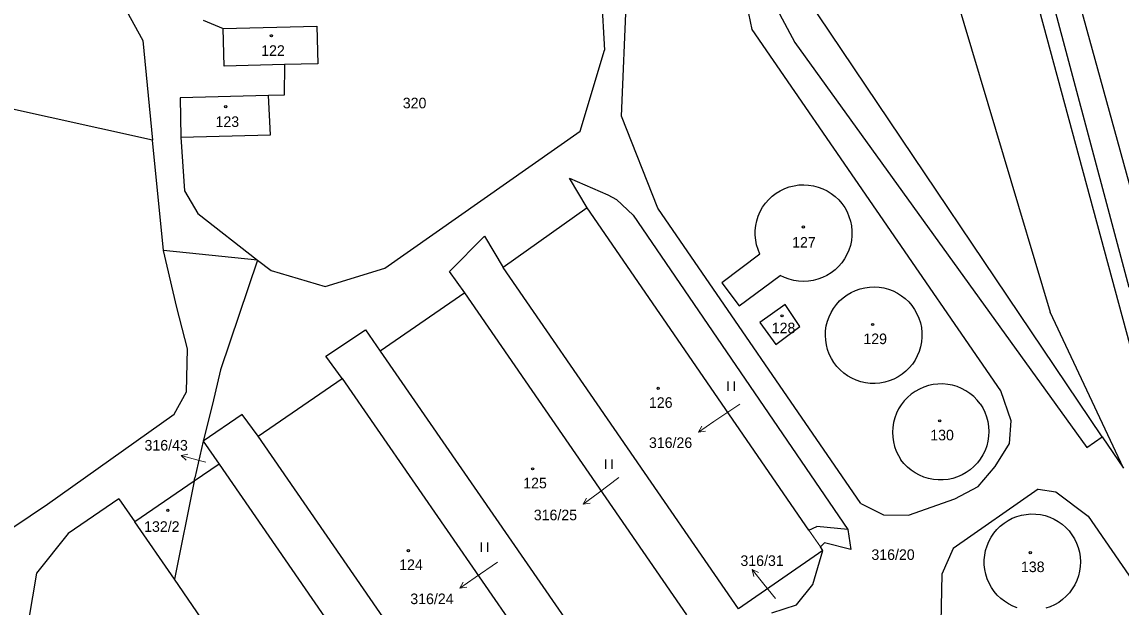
# Model space of a CAD drawing. Extents: x -765428 to -762163, y -1107632 to -1104975.
# Drawn here: x -763826.2 to -763649.6, y -1106955.1 to -1106861.1 of the extents above; entities that cross this region are included whole.
import ezdxf
from ezdxf.enums import TextEntityAlignment as Align

# ---------------------------------------------------------------- set-up
doc = ezdxf.new("R2010")
doc.units = 0
doc.header["$LTSCALE"] = 0.68
for name, color, linetype, lineweight in [('1', 7, 'Continuous', 25), ('3', 7, 'Continuous', 25), ('4', 7, 'Continuous', 13), ('5', 7, 'Continuous', 25), ('7', 7, 'Continuous', 13)]:
    doc.layers.add(name, color=color, linetype=linetype, lineweight=lineweight)
doc.layers.add('2', color=7, linetype='Continuous')

msp = doc.modelspace()

# ---------------------------------------------------------------- linework, layer by layer
at = {"layer": '1'}
for p, q in [((-763729.84, -1106876.2), (-763724.72, -1106752.96)), ((-763674.43, -1106815.86), (-763648.22, -1106912.79)), ((-763671.61, -1106816.67), (-763648.34, -1106903.67)), ((-763685.8, -1106824.68), (-763661.01, -1106907.69)), ((-763658.9, -1106848.62), (-763644.06, -1106902.56)), ((-763733.28, -1106852.94), (-763732.61, -1106865.62)), ((-763652.64, -1106927.72), (-763703.4, -1106852.31)), ((-763810.93, -1106856.45), (-763806.76, -1106864.07)), ((-763708.89, -1106862.32), (-763709.99, -1106856.84)), ((-763705.7, -1106857.45), (-763702.02, -1106864.4)), ((-763797.08, -1106860.79), (-763793.86, -1106862.12)), ((-763793.86, -1106862.12), (-763778.83, -1106861.76)), ((-763793.68, -1106868.18), (-763793.86, -1106862.12)), ((-763778.83, -1106861.76), (-763778.65, -1106867.81)), ((-763668.92, -1106920.34), (-763708.89, -1106862.32)), ((-763806.76, -1106864.07), (-763805.23, -1106880.1)), ((-763736.52, -1106878.66), (-763732.61, -1106865.62)), ((-763702.02, -1106864.4), (-763655.1, -1106929.44)), ((-763784.03, -1106867.94), (-763793.68, -1106868.18)), ((-763784.03, -1106867.94), (-763784.07, -1106872.85)), ((-763778.65, -1106867.81), (-763784.03, -1106867.94)), ((-763805.23, -1106880.1), (-763850.56, -1106870)), ((-763784.07, -1106872.85), (-763786.56, -1106872.91)), ((-763786.56, -1106872.91), (-763800.79, -1106873.27)), ((-763800.79, -1106873.27), (-763800.66, -1106879.61)), ((-763786.26, -1106879.25), (-763786.56, -1106872.91)), ((-763724.04, -1106891), (-763729.84, -1106876.2)), ((-763800.66, -1106879.61), (-763786.26, -1106879.25)), ((-763800.66, -1106879.61), (-763800.09, -1106888.21)), ((-763767.86, -1106900.62), (-763736.52, -1106878.66)), ((-763803.44, -1106897.82), (-763805.23, -1106880.1)), ((-763738.22, -1106886.17), (-763732.08, -1106888.88)), ((-763735.38, -1106890.95), (-763738.22, -1106886.17)), ((-763800.09, -1106888.21), (-763797.94, -1106891.84)), ((-763732.08, -1106888.88), (-763730.66, -1106889.62)), ((-763730.66, -1106889.62), (-763728, -1106892.15)), ((-763797.94, -1106891.84), (-763788.32, -1106899.34)), ((-763735.38, -1106890.95), (-763748.9, -1106900.52)), ((-763699.75, -1106942.73), (-763735.38, -1106890.95)), ((-763728, -1106892.15), (-763693.51, -1106942.61)), ((-763691.41, -1106938.45), (-763724.04, -1106891)), ((-763757.48, -1106901.19), (-763751.89, -1106895.5)), ((-763751.89, -1106895.5), (-763748.9, -1106900.52)), ((-763801.32, -1106906.94), (-763803.44, -1106897.82)), ((-763788.32, -1106899.34), (-763803.44, -1106897.82)), ((-763788.32, -1106899.34), (-763794.28, -1106917)), ((-763788.32, -1106899.34), (-763786.17, -1106901.01)), ((-763707.61, -1106898.39), (-763713.73, -1106902.99)), ((-763786.17, -1106901.01), (-763777.49, -1106903.61)), ((-763777.49, -1106903.61), (-763767.86, -1106900.62)), ((-763711.05, -1106955.37), (-763748.9, -1106900.52)), ((-763755.04, -1106904.61), (-763757.48, -1106901.19)), ((-763710.95, -1106906.71), (-763704.38, -1106901.81)), ((-763755.04, -1106904.61), (-763768.62, -1106914)), ((-763719.34, -1106956.36), (-763755.04, -1106904.61)), ((-763713.73, -1106902.99), (-763710.95, -1106906.71)), ((-763799.59, -1106913.59), (-763801.32, -1106906.94)), ((-763649.23, -1106932.76), (-763661.01, -1106907.69)), ((-763707.64, -1106909.36), (-763705.08, -1106912.93)), ((-763777.39, -1106914.8), (-763771.01, -1106910.53)), ((-763771.01, -1106910.53), (-763768.62, -1106914)), ((-763705.08, -1106912.93), (-763701.2, -1106910.04)), ((-763799.77, -1106920.51), (-763799.59, -1106913.59)), ((-763774.76, -1106918.36), (-763777.39, -1106914.8)), ((-763768.62, -1106914), (-763730.65, -1106968.92)), ((-763794.28, -1106917), (-763795.57, -1106922.48)), ((-763788.24, -1106927.65), (-763774.76, -1106918.36)), ((-763774.76, -1106918.36), (-763738.81, -1106970.36)), ((-763801.72, -1106924.09), (-763799.77, -1106920.51)), ((-763667.27, -1106925.18), (-763668.92, -1106920.34)), ((-763795.57, -1106922.48), (-763797.06, -1106928.41)), ((-763822.07, -1106938.55), (-763801.72, -1106924.09)), ((-763790.83, -1106924.13), (-763797.06, -1106928.41)), ((-763788.24, -1106927.65), (-763790.83, -1106924.13)), ((-763667.5, -1106928.81), (-763667.27, -1106925.18)), ((-763797.06, -1106928.41), (-763798.41, -1106934.35)), ((-763797.06, -1106928.41), (-763794.52, -1106932.12)), ((-763750.25, -1106982.66), (-763788.24, -1106927.65)), ((-763669.8, -1106932.49), (-763667.5, -1106928.81)), ((-763655.1, -1106929.44), (-763652.64, -1106927.72)), ((-763652.64, -1106927.72), (-763649.23, -1106932.76)), ((-763794.52, -1106932.12), (-763798.51, -1106934.86)), ((-763794.52, -1106932.12), (-763758.29, -1106984.57)), ((-763672.58, -1106935.74), (-763669.8, -1106932.49)), ((-763798.51, -1106934.86), (-763798.41, -1106934.35)), ((-763798.51, -1106934.86), (-763808.06, -1106941.41)), ((-763662.89, -1106936.13), (-763676.56, -1106945.69)), ((-763676.32, -1106937.69), (-763672.58, -1106935.74)), ((-763662.89, -1106936.13), (-763660.09, -1106936.58)), ((-763810.62, -1106937.71), (-763818.75, -1106943.29)), ((-763810.62, -1106937.71), (-763808.06, -1106941.41)), ((-763683.77, -1106940.31), (-763676.32, -1106937.69)), ((-763660.09, -1106936.58), (-763654.9, -1106940.48)), ((-763827.64, -1106942.32), (-763822.07, -1106938.55)), ((-763691.41, -1106938.45), (-763687.78, -1106940.28)), ((-763687.78, -1106940.28), (-763683.77, -1106940.31)), ((-763654.9, -1106940.48), (-763622.05, -1106988.12)), ((-763818.75, -1106943.29), (-763823.87, -1106949.65)), ((-763699.75, -1106942.73), (-763698.45, -1106942.12)), ((-763693.51, -1106942.61), (-763698.45, -1106942.12)), ((-763693.51, -1106942.61), (-763693.04, -1106945.86)), ((-763697.9, -1106945.43), (-763697.22, -1106944.76)), ((-763693.04, -1106945.86), (-763697.22, -1106944.76)), ((-763697.52, -1106945.98), (-763711.05, -1106955.37)), ((-763699.14, -1106951.48), (-763697.52, -1106945.98)), ((-763697.52, -1106945.98), (-763697.9, -1106945.43)), ((-763676.56, -1106945.69), (-763678.37, -1106949.8)), ((-763823.87, -1106949.65), (-763825.16, -1106957.25)), ((-763678.37, -1106949.8), (-763678.57, -1106957.56)), ((-763770.1, -1106996.39), (-763801.7, -1106950.62)), ((-763701.74, -1106954.74), (-763699.14, -1106951.48)), ((-763705.7, -1106956.04), (-763701.74, -1106954.74))]:
    msp.add_line(p, q, dxfattribs=at)
for points in [[(-763707.61, -1106898.39), (-763707.915, -1106897.665), (-763708.146, -1106896.914), (-763708.299, -1106896.143), (-763708.374, -1106895.36), (-763708.369, -1106894.574), (-763708.284, -1106893.792), (-763708.122, -1106893.023), (-763707.882, -1106892.275), (-763707.568, -1106891.554), (-763707.183, -1106890.869), (-763706.73, -1106890.226), (-763706.215, -1106889.632), (-763705.642, -1106889.093), (-763705.018, -1106888.615), (-763704.349, -1106888.203), (-763703.641, -1106887.86), (-763702.903, -1106887.59), (-763702.141, -1106887.397), (-763701.363, -1106887.281), (-763700.578, -1106887.245), (-763699.793, -1106887.288), (-763699.016, -1106887.41), (-763698.256, -1106887.61), (-763697.52, -1106887.886), (-763696.815, -1106888.235), (-763696.15, -1106888.653), (-763695.53, -1106889.136), (-763694.962, -1106889.68), (-763694.451, -1106890.278), (-763694.004, -1106890.924), (-763693.625, -1106891.613), (-763693.317, -1106892.336), (-763693.083, -1106893.087), (-763692.927, -1106893.857), (-763692.849, -1106894.64), (-763692.851, -1106895.426), (-763692.932, -1106896.208), (-763693.092, -1106896.977), (-763693.329, -1106897.727), (-763693.64, -1106898.449), (-763694.023, -1106899.136), (-763694.473, -1106899.78), (-763694.986, -1106900.376), (-763695.557, -1106900.917), (-763696.179, -1106901.398), (-763696.846, -1106901.813), (-763697.553, -1106902.158), (-763698.29, -1106902.431), (-763699.051, -1106902.627), (-763699.828, -1106902.746), (-763700.614, -1106902.785), (-763701.399, -1106902.745), (-763702.176, -1106902.626), (-763702.937, -1106902.429), (-763703.674, -1106902.156), (-763704.38, -1106901.81)], [(-763695.74, -1106915.8), (-763696.143, -1106915.145), (-763696.479, -1106914.453), (-763696.745, -1106913.731), (-763696.939, -1106912.986), (-763697.057, -1106912.226), (-763697.1, -1106911.458), (-763697.066, -1106910.689), (-763696.957, -1106909.928), (-763696.773, -1106909.181), (-763696.515, -1106908.456), (-763696.187, -1106907.76), (-763695.792, -1106907.1), (-763695.333, -1106906.482), (-763694.816, -1106905.913), (-763694.245, -1106905.398), (-763693.625, -1106904.942), (-763692.963, -1106904.549), (-763692.266, -1106904.224), (-763691.54, -1106903.97)], [(-763691.54, -1106903.97), (-763690.787, -1106903.788), (-763690.019, -1106903.682), (-763689.244, -1106903.654), (-763688.471, -1106903.702), (-763687.706, -1106903.828), (-763686.958, -1106904.029), (-763686.233, -1106904.304), (-763685.54, -1106904.65), (-763684.884, -1106905.064), (-763684.273, -1106905.54), (-763683.713, -1106906.076), (-763683.209, -1106906.664), (-763682.766, -1106907.3), (-763682.389, -1106907.977), (-763682.081, -1106908.688), (-763681.845, -1106909.427), (-763681.685, -1106910.185), (-763681.601, -1106910.955), (-763681.594, -1106911.73), (-763681.665, -1106912.502), (-763681.812, -1106913.263), (-763682.035, -1106914.005), (-763682.33, -1106914.722), (-763682.696, -1106915.405), (-763683.127, -1106916.049), (-763683.621, -1106916.646), (-763684.172, -1106917.191), (-763684.775, -1106917.678), (-763685.423, -1106918.103), (-763686.111, -1106918.461), (-763686.83, -1106918.748), (-763687.575, -1106918.962), (-763688.338, -1106919.101), (-763689.11, -1106919.163), (-763689.885, -1106919.148), (-763690.654, -1106919.056), (-763691.411, -1106918.887), (-763692.146, -1106918.643), (-763692.854, -1106918.328), (-763693.527, -1106917.943), (-763694.158, -1106917.493), (-763694.741, -1106916.982), (-763695.27, -1106916.416), (-763695.74, -1106915.8)], [(-763701.2, -1106910.04), (-763703.55, -1106906.5), (-763707.64, -1106909.36)], [(-763672.23, -1106922.43), (-763672.722, -1106921.824), (-763673.272, -1106921.27), (-763673.875, -1106920.774), (-763674.524, -1106920.341), (-763675.214, -1106919.975), (-763675.936, -1106919.68), (-763676.685, -1106919.458), (-763677.452, -1106919.313), (-763678.23, -1106919.244), (-763679.01, -1106919.254), (-763679.786, -1106919.343), (-763680.549, -1106919.508), (-763681.291, -1106919.748), (-763682.006, -1106920.062), (-763682.686, -1106920.446), (-763683.324, -1106920.896), (-763683.914, -1106921.407), (-763684.45, -1106921.975), (-763684.926, -1106922.593), (-763685.338, -1106923.256), (-763685.682, -1106923.957), (-763685.953, -1106924.689), (-763686.151, -1106925.444), (-763686.271, -1106926.215), (-763686.314, -1106926.995), (-763686.279, -1106927.775), (-763686.166, -1106928.547), (-763685.977, -1106929.304), (-763685.712, -1106930.039), (-763685.375, -1106930.743), (-763684.97, -1106931.41)], [(-763672.23, -1106922.43), (-763671.814, -1106923.097), (-763671.467, -1106923.803), (-763671.193, -1106924.541), (-763670.995, -1106925.302), (-763670.875, -1106926.079), (-763670.834, -1106926.864), (-763670.871, -1106927.65), (-763670.988, -1106928.427), (-763671.183, -1106929.189), (-763671.453, -1106929.928), (-763671.797, -1106930.635), (-763672.21, -1106931.305), (-763672.688, -1106931.929), (-763673.227, -1106932.502), (-763673.821, -1106933.017), (-763674.464, -1106933.47), (-763675.149, -1106933.856), (-763675.87, -1106934.171), (-763676.619, -1106934.412), (-763677.388, -1106934.576), (-763678.169, -1106934.662), (-763678.956, -1106934.668), (-763679.739, -1106934.595), (-763680.511, -1106934.444), (-763681.263, -1106934.216), (-763681.989, -1106933.913), (-763682.681, -1106933.538), (-763683.331, -1106933.096), (-763683.933, -1106932.59), (-763684.481, -1106932.026), (-763684.97, -1106931.41)], [(-763798.51, -1106934.86), (-763801.7, -1106950.62), (-763808.06, -1106941.41)], [(-763670.47, -1106943.87), (-763670.04, -1106943.23), (-763669.548, -1106942.636), (-763669, -1106942.094), (-763668.4, -1106941.609), (-763667.755, -1106941.186), (-763667.071, -1106940.83), (-763666.355, -1106940.543), (-763665.614, -1106940.33), (-763664.856, -1106940.191), (-763664.087, -1106940.128), (-763663.316, -1106940.143), (-763662.55, -1106940.234), (-763661.797, -1106940.4), (-763661.065, -1106940.641), (-763660.36, -1106940.954), (-763659.69, -1106941.336), (-763659.061, -1106941.782), (-763658.479, -1106942.288), (-763657.951, -1106942.851), (-763657.482, -1106943.462), (-763657.076, -1106944.118), (-763656.737, -1106944.811), (-763656.469, -1106945.534), (-763656.274, -1106946.28), (-763656.155, -1106947.042), (-763656.112, -1106947.812), (-763656.146, -1106948.582), (-763656.256, -1106949.345), (-763656.442, -1106950.094), (-763656.702, -1106950.82), (-763657.032, -1106951.517), (-763657.431, -1106952.177), (-763657.893, -1106952.794), (-763658.414, -1106953.363), (-763658.99, -1106953.876), (-763659.613, -1106954.33), (-763660.279, -1106954.719), (-763660.98, -1106955.04)], [(-763666.266, -1106955.205), (-763666.985, -1106954.927), (-763667.673, -1106954.58), (-763668.323, -1106954.166), (-763668.929, -1106953.689), (-763669.484, -1106953.154), (-763669.983, -1106952.567), (-763670.421, -1106951.933), (-763670.794, -1106951.258), (-763671.098, -1106950.55), (-763671.329, -1106949.815), (-763671.487, -1106949.06), (-763671.568, -1106948.294), (-763671.573, -1106947.523), (-763671.5, -1106946.755), (-763671.352, -1106945.999), (-763671.13, -1106945.261), (-763670.835, -1106944.549), (-763670.47, -1106943.87)], [(-763660.98, -1106955.04), (-763661.709, -1106955.29)]]:
    msp.add_lwpolyline(points, dxfattribs=at)
at = {"layer": '3'}
for p, q in [((-763712.721, -1106920.37), (-763712.721, -1106918.87)), ((-763711.72, -1106920.37), (-763711.72, -1106918.87)), ((-763732.361, -1106932.87), (-763732.361, -1106931.37)), ((-763731.36, -1106932.87), (-763731.36, -1106931.37)), ((-763752.351, -1106946.21), (-763752.351, -1106944.71)), ((-763751.35, -1106946.21), (-763751.35, -1106944.71))]:
    msp.add_line(p, q, dxfattribs=at)
at = {"layer": '4'}
msp.add_line((-763699.75, -1106942.73), (-763697.9, -1106945.43), dxfattribs=at)
at = {"layer": '5'}
for centre in [(-763786.1168, -1106863.3092), (-763793.4468, -1106874.6992), (-763700.6368, -1106894.0292), (-763704.0668, -1106908.2992), (-763689.5068, -1106909.6992), (-763723.9768, -1106919.9592), (-763678.7368, -1106925.1792), (-763744.1368, -1106932.8892), (-763802.7568, -1106939.5492), (-763764.1068, -1106946.0192), (-763664.1768, -1106946.3492)]:
    msp.add_circle(centre, 0.175, dxfattribs=at)
at = {"layer": '7'}
for p, q in [((-763717.498, -1106926.978), (-763716.388, -1106926.833)), ((-763800.629, -1106930.743), (-763799.791, -1106931.486)), ((-763735.997, -1106938.576), (-763734.896, -1106938.373)), ((-763708.859, -1106949.068), (-763708.617, -1106950.161)), ((-763755.828, -1106952.071), (-763754.721, -1106951.907))]:
    msp.add_line(p, q, dxfattribs=at)
for points in [[(-763710.83, -1106922.5), (-763715.01, -1106925.3), (-763717.498, -1106926.978), (-763716.948, -1106926.003)], [(-763796.64, -1106931.8), (-763797.73, -1106931.52), (-763800.629, -1106930.743), (-763799.532, -1106930.519)], [(-763730.27, -1106934.26), (-763733.6, -1106936.77), (-763735.997, -1106938.576), (-763735.498, -1106937.573)], [(-763749.8, -1106947.89), (-763753.37, -1106950.35), (-763755.828, -1106952.071), (-763755.295, -1106951.087)], [(-763705.11, -1106953.73), (-763706.97, -1106951.4), (-763708.859, -1106949.068), (-763707.839, -1106949.531)]]:
    msp.add_lwpolyline(points, dxfattribs=at)

# ---------------------------------------------------------------- texts
at = {"layer": '2'}
for s, p in [('122', (-763787.75, -1106866.535)), ('320', (-763765, -1106874.965)), ('123', (-763795.09, -1106877.965)), ('128', (-763705.72, -1106911.105)), ('129', (-763691, -1106912.845)), ('126', (-763725.45, -1106923.085)), ('130', (-763680.25, -1106928.305)), ('125', (-763745.65, -1106936.015)), ('132/2', (-763806.56, -1106943.005)), ('316/20', (-763689.71, -1106947.515)), ('124', (-763765.58, -1106949.145)), ('138', (-763665.68, -1106949.475))]:
    msp.add_text(s, height=1.7, dxfattribs=at).set_placement(p)
msp.add_text('127', height=1.7, dxfattribs=at).set_placement((-763700.549, -1106897.345), align=Align.CENTER)
for s, p in [('316/43', (-763799.539, -1106929.945)), ('316/26', (-763718.499, -1106929.535)), ('316/25', (-763736.999, -1106941.145)), ('316/31', (-763703.799, -1106948.485)), ('316/24', (-763756.839, -1106954.615))]:
    msp.add_text(s, height=1.7, dxfattribs=at).set_placement(p, align=Align.RIGHT)

doc.saveas('drawing.dxf')
